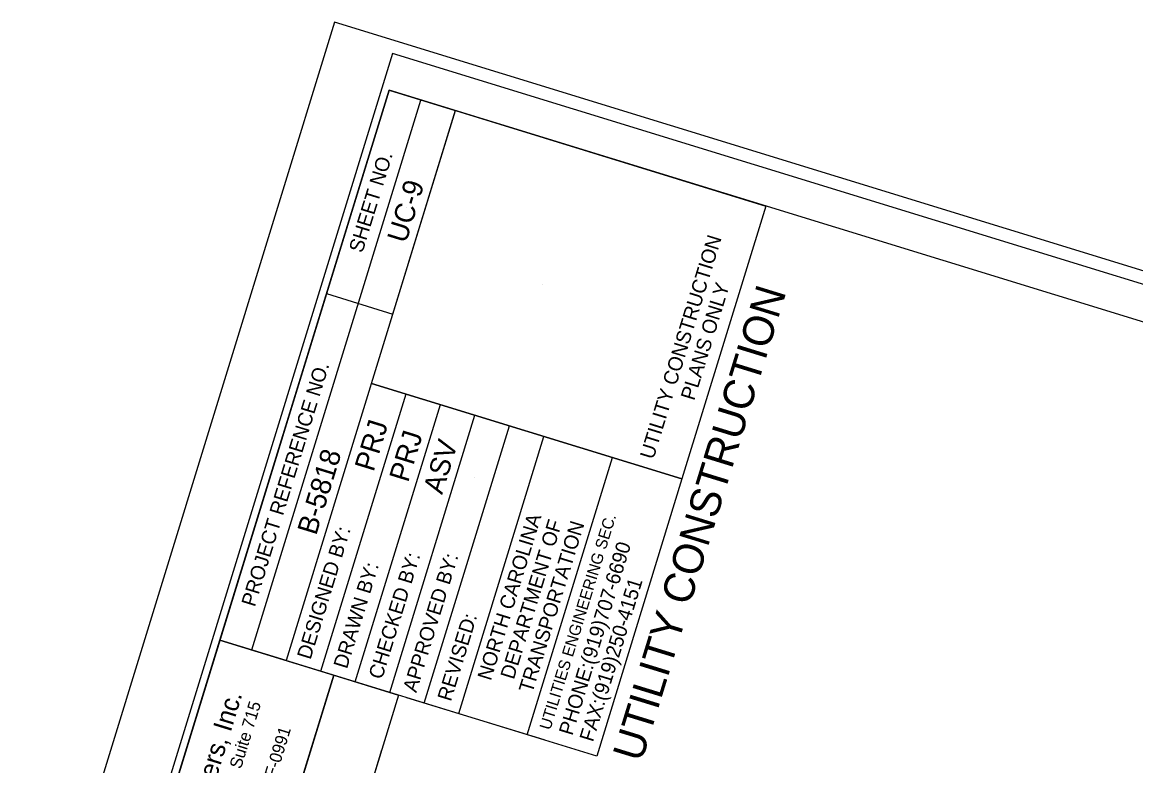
# Model space of a CAD drawing. Extents: x 1439200 to 1642353, y 394562 to 606444.
# Drawn here: x 1641889.6 to 1642044.2, y 395231.5 to 395334.8 of the extents above; entities that cross this region are included whole.
import ezdxf

# ---------------------------------------------------------------- set-up
doc = ezdxf.new("R2010")
doc.units = 0
for name, color, linetype in [('North Arrow NAD83 CELL', 7, 'Continuous'), ('Old_Level_60', 7, 'Continuous'), ('Sheet Data Field CELL', 7, 'Continuous'), ('Sheet Plot Border Inside CELL', 7, 'Continuous'), ('Sheet Plot Border Outside CELL', 7, 'Continuous'), ('Sheet Sticker Exception Certification CELL', 7, 'Continuous'), ('UC Plan Sheet 34 CELL', 7, 'Continuous')]:
    doc.layers.add(name, color=color, linetype=linetype)

msp = doc.modelspace()

# ---------------------------------------------------------------- linework, layer by layer
at = {"layer": 'North Arrow NAD83 CELL'}
for p, q in [((1641962.02, 395235.14), (1641942.96, 395241)), ((1641939.44, 395233.69), (1641927.81, 395195.87))]:
    msp.add_line(p, q, dxfattribs=at)
at = {"layer": 'Old_Level_60'}
msp.add_lwpolyline([(1641893.47, 395172.51), (1641916.99, 395248.99), (1641932.81, 395244.12), (1641909.29, 395167.64)], close=True, dxfattribs=at)
at = {"layer": 'Sheet Plot Border Inside CELL'}
msp.add_lwpolyline([(1641940.98, 395330.47), (1641745.02, 394693.33), (1642148.41, 394569.26), (1642344.38, 395206.4)], close=True, dxfattribs=at)
at = {"layer": 'Sheet Plot Border Outside CELL'}
msp.add_lwpolyline([(1641932.93, 395334.83), (1641734.91, 394691), (1642155.47, 394561.65), (1642353.49, 395205.48)], close=True, dxfattribs=at)
at = {"layer": 'Sheet Sticker Exception Certification CELL'}
for p, q in [((1641909.29, 395167.64), (1641932.81, 395244.12)), ((1641932.82, 395244.12), (1641941.8, 395241.36)), ((1641941.8, 395241.36), (1641918.28, 395164.88))]:
    msp.add_line(p, q, dxfattribs=at)
at = {"layer": 'UC Plan Sheet 34 CELL'}
for p, q in [((1641921.43, 395247.63), (1641944.92, 395324.03)), ((1641942.96, 395309.13), (1641942.96, 395309.13)), ((1641961.76, 395298.44), (1641961.76, 395298.44)), ((1641931.8, 395297.13), (1641941.02, 395294.29)), ((1641931.01, 395244.68), (1641942.85, 395283.19)), ((1641935.8, 395243.21), (1641947.64, 395281.72)), ((1641940.58, 395241.73), (1641952.43, 395280.25)), ((1641945.37, 395240.26), (1641957.22, 395278.77)), ((1641938.03, 395276.04), (1641938.03, 395276.04)), ((1641950.17, 395238.79), (1641962.01, 395277.3)), ((1641942.82, 395274.57), (1641942.82, 395274.57)), ((1641947.61, 395273.09), (1641947.61, 395273.09)), ((1641959.67, 395235.86), (1641971.51, 395274.38)), ((1641952.4, 395271.62), (1641952.4, 395271.62)), ((1641931.21, 395270.96), (1641931.21, 395270.96))]:
    msp.add_line(p, q, dxfattribs=at)
msp.add_lwpolyline([(1641940.49, 395325.39), (1641764.1, 394751.91), (1642165.54, 394628.44), (1642341.93, 395201.92)], close=True, dxfattribs=at)
for points in [[(1641916.99, 395248.99), (1641940.49, 395325.39), (1641949.69, 395322.56)], [(1641949.69, 395322.56), (1641926.19, 395246.16), (1641916.99, 395248.99)], [(1641992.82, 395309.3), (1641981.17, 395271.41), (1641938.06, 395284.67), (1641949.71, 395322.56)], [(1641949.71, 395322.56), (1641992.82, 395309.3)], [(1641938.04, 395284.67), (1641981.17, 395271.41), (1641969.33, 395232.89), (1641916.99, 395248.99)]]:
    msp.add_lwpolyline(points, dxfattribs=at)

# ---------------------------------------------------------------- texts
at = {"layer": 'Old_Level_60'}
for s, height, p in [('STV Engineers, Inc.', 2.6, (1641911.05, 395211.92)), ('900 West Trade St., Suite 715', 1.7, (1641913.79, 395211.08)), ('NC License Number F-0991', 1.7, (1641918.57, 395209.61))]:
    msp.add_text(s, height=height, rotation=72.9038, dxfattribs=at).set_placement(p)
at = {"layer": 'Sheet Data Field CELL'}
for s, p in [('UC-9', (1641942.85, 395304.02)), ('PRJ', (1641938.33, 395272.28)), ('PRJ', (1641943.13, 395270.8)), ('ASV', (1641947.86, 395269.13)), ('B-5818', (1641930.37, 395263.45))]:
    msp.add_text(s, height=2.8, rotation=72.9038, dxfattribs=at).set_placement(p)
at = {"layer": 'UC Plan Sheet 34 CELL'}
for s, height, p in [('SHEET NO.', 2.005, (1641936.79, 395302.69)), ('UTILITY CONSTRUCTION', 2.0046, (1641977.21, 395274)), ('UTILITY CONSTRUCTION', 4.25, (1641975.56, 395231.91)), ('PLANS ONLY', 2.005, (1641982.87, 395282.18)), ('PROJECT REFERENCE NO.', 2.0046, (1641921.85, 395253.52)), ('NORTH CAROLINA', 2.0046, (1641954.63, 395243.27)), ('DEPARTMENT OF', 2.0046, (1641957.82, 395243.43)), ('TRANSPORTATION', 2.0046, (1641960.39, 395241.54)), ('UTILITIES ENGINEERING SEC.', 1.6037, (1641962.88, 395236.41)), ('DESIGNED BY:', 2.0046, (1641929.58, 395246.19)), ('PHONE:(919)707-6690', 2.0046, (1641965.94, 395235.64)), ('CHECKED BY:', 2.0046, (1641939.51, 395243.43)), ('APPROVED BY:', 2.0046, (1641944.28, 395241.61)), ('DRAWN BY:', 2.005, (1641934.64, 395244.91)), ('FAX:(919)250-4151', 2.0046, (1641968.81, 395234.75)), ('REVISED:', 2.005, (1641949.08, 395240.38))]:
    msp.add_text(s, height=height, rotation=72.9038, dxfattribs=at).set_placement(p)

doc.saveas('drawing.dxf')
